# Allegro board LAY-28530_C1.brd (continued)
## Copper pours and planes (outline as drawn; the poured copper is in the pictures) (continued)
GND on L2_GND: 207.32,167.46 214.61,167.46 214.61,1.83 213.84,1.06 97.34,1.06 96.58,1.83 3.49,1.83 1.45,3.86 1.45,166.93 1.83,167.31 70.16,167.31 70.16,153.46 66.86,150.16 66.86,129.21 88.96,129.21 92.26,132.51 92.26,156.51 138.74,156.51 140.58,154.67 167.63,154.67 171.76,158.8 171.76,165.28 173.03,166.55 180.52,166.55 182.56,164.51 182.56,161.97 184.97,159.56 190.94,159.56 191.95,160.58 201.73,160.58 202.62,159.69 206.56,159.69 207.32,160.45 ; 9 cut-outs
GND on L5_PWR: 112.82,41.35 112.82,35.42 108.74,31.34 108.74,19.1 114.97,12.88 174.94,12.88 174.94,30.91 165.16,30.91 164.39,31.67 164.39,41.07 156.65,48.82 156.65,52.75 150.04,59.36 146.87,59.36 146.36,59.87 145.22,59.87 143.68,61.4 136.3,61.4 135.42,60.52 132.47,60.52 128.18,56.23 127.7,56.23
GND on L5_PWR: 67.49,167.18 1.96,167.18 1.07,166.29 1.07,4.62 3.1,2.59 70.41,2.59 71.68,3.86 71.68,32.94 53.02,51.61 23.81,51.61 22.28,53.13 22.28,98.09 41.97,117.78 41.97,147.75 44.38,150.16 66.86,150.16 68.26,151.56 68.26,166.42 ; 4 cut-outs
GND on L5_PWR: 171.89,159.56 207.45,159.56 207.45,167.43 214.94,167.43 215.19,167.18 215.19,151.56 208.97,151.56 208.97,153.21 174.05,153.21 173.92,153.08 173.92,148.38 172.14,148.38 167.32,143.56 138.87,143.56 138.87,130.35 92.26,130.35 92.26,148.26 93.15,149.15 100.26,149.15 106.61,155.5 167.82,155.5
GND_EARTH on TOP: 188.91,160.07 188.91,165.66 189.79,166.55 206.05,166.55 206.56,166.04 206.56,160.45 205.67,159.56 203.26,159.56 202.24,160.58 191.95,160.58 190.94,159.56 189.41,159.56
GND_EARTH on BOTTOM: 124.39,165.78 124.39,161.59 128.71,161.59 128.71,165.78
GND_EARTH on BOTTOM: 111.18,168.58 111.56,168.96 117.79,168.96 118.55,168.2 118.55,161.47 118.42,161.34 111.18,161.34
GND_EARTH on BOTTOM: 168.97,157.91 168.97,161.34 168.46,161.85 164.14,161.85 163.51,161.21 163.51,158.04 163.89,157.66 168.71,157.66
GND_EARTH on L2_GND: 141.92,157.4 141.41,157.91 141.41,162.48 140.39,163.5 92.26,163.5 92.13,163.62 92.13,168.83 206.81,168.83 206.81,161.08 205.92,160.2 203.13,160.2 201.86,161.47 191.83,161.47 190.56,160.2 185.73,160.2 183.44,162.48 183.44,165.66 181.67,167.43 172.4,167.43 170.87,165.91 170.87,159.94 168.33,157.4 ; 1 cut-out
GND_EARTH on L5_PWR: 159.06,167.46 206.56,167.46 206.56,160.45 206.3,160.2 171.13,160.2 168.33,157.4 158.81,157.4 158.55,157.66 158.55,166.95
GND_SIGNAL on TOP: 82.61,150.16 83.24,149.53 83.24,146.1 82.86,145.72 79.3,145.72 78.92,145.34 78.92,143.69 78.8,143.56 75.75,143.56 75.49,143.81 75.49,152.83 75.75,153.08 82.1,153.08 82.61,152.58
GND_SIGNAL on TOP: 78.54,139.24 79.94,139.24 80.7,138.48 80.7,134.92 81.08,134.54 86.67,134.54 87.18,134.03 87.18,132.26 86.04,131.11 79.3,131.11 78.16,132.26 78.16,138.86
GND_SIGNAL on BOTTOM: 78.03,135.18 78.03,130.48 78.8,129.72 87.81,129.72 88.19,130.1 88.19,135.18 87.56,135.81 78.67,135.81
GND_SIGNAL on L2_GND: 71.43,151.18 68.26,148 68.26,130.1 87.94,130.1 91.37,133.53 91.37,168.15 90.3,169.21 72.07,169.21 71.43,168.58
GND_SIGNAL on L5_PWR: 68.26,138.61 68.26,148 71.43,151.18 71.43,168.58 72.07,169.21 90.48,169.21 90.73,168.96 91.24,168.96 91.37,168.83 91.37,138.61
12 on TOP: 73.34,165.66 73.34,168.83 73.46,168.96 76.89,168.96 77.15,168.7 77.15,165.66 76.76,165.28 73.72,165.28
12 on BOTTOM: 149.15,165.15 149.15,166.8 148.9,167.05 146.49,167.05 146.23,166.8 146.23,164.89 146.49,164.64 147.5,164.64 147.88,165.02 149.03,165.02
12 on BOTTOM: 92,152.45 94.8,152.45 94.93,152.32 94.93,151.05 94.8,150.92 91.88,150.92 91.75,151.05 91.75,152.19
12 on BOTTOM: 73.34,165.66 73.34,168.83 73.46,168.96 76.89,168.96 77.15,168.7 77.15,165.66 76.76,165.28 73.72,165.28
12 on L4_INT2: 86.04,161.21 78.29,168.96 74.86,168.96 74.61,168.7 74.61,167.05 83.62,158.04 89.59,158.04 90.23,157.4 90.23,153.97 93.53,150.67 94.8,150.67 95.05,150.92 95.05,152.58 92.77,154.86 92.77,158.67 90.23,161.21
12 on L5_PWR: 147.76,166.16 146.23,166.16 145.22,165.15 140.9,165.15 136.71,160.96 102.42,160.96 99.05,157.59 99.05,154.92 96.96,152.83 93.02,152.83 92.64,152.45 92.64,150.92 93.4,150.16 99.62,150.16 106.1,156.64 143.44,156.64 148.01,161.21 148.01,165.91
34 on TOP: 82.23,165.66 82.23,168.83 82.35,168.96 85.78,168.96 86.04,168.7 86.04,165.66 85.65,165.28 82.61,165.28
34 on BOTTOM: 82.23,165.66 82.23,168.83 82.35,168.96 85.78,168.96 86.04,168.7 86.04,165.66 85.65,165.28 82.61,165.28
34 on BOTTOM: 149.79,164.77 151.82,164.77 151.95,164.89 151.95,166.8 151.69,167.05 149.54,167.05 149.41,166.93 149.41,165.15
34 on BOTTOM: 102.55,152.45 105.34,152.45 105.47,152.32 105.47,151.31 105.21,151.05 102.55,151.05 102.42,151.18 102.42,152.32
34 on L4_INT2: 84.77,168.96 89.97,168.96 92.51,166.42 92.51,162.74 95.05,160.2 99.5,160.2 127.44,160.2 127.56,160.07 134.93,160.07 138.99,164.13 147.63,164.13 148.65,165.15 148.65,167.05 149.41,167.82 151.31,167.82 151.95,167.18 151.95,163.24 148.9,160.2 142.17,160.2 138.87,156.89 106.1,156.89 104.96,155.75 104.96,154.73 106.1,153.59 106.1,150.92 105.85,150.67 103.43,150.67 103.18,150.92 103.18,152.96 98.86,157.27 95.05,157.27 90.61,161.72 86.54,161.72 84.26,164.01 84.26,168.45
56 on TOP: 77.78,165.66 77.78,168.83 77.91,168.96 81.34,168.96 81.59,168.7 81.59,165.66 81.21,165.28 78.16,165.28
56 on BOTTOM: 77.78,165.66 77.78,168.83 77.91,168.96 81.34,168.96 81.59,168.7 81.59,165.66 81.21,165.28 78.16,165.28
56 on BOTTOM: 152.33,164.77 154.23,164.77 154.49,165.02 154.49,166.93 154.36,167.05 152.33,167.05 152.2,166.93 152.2,164.89
56 on BOTTOM: 91.88,156.89 94.67,156.89 94.8,157.02 94.8,158.42 94.54,158.67 91.75,158.67 91.62,158.54 91.62,157.15
56 on L3_INT1: 85.91,157.4 79.69,163.62 79.69,168.7 80.07,169.09 83.88,169.09 84.38,168.58 84.38,166.29 88.19,162.48 90.99,162.48 95.05,158.42 95.05,156.51 94.93,156.39 92.13,156.39 91.12,157.4
56 on L5_PWR: 93.15,156.64 96.07,156.64 102.67,163.24 135.95,163.24 139.38,166.67 147.88,166.67 149.92,164.64 154.23,164.64 154.62,165.02 154.62,168.45 154.11,168.96 94.67,168.96 92.64,166.93 92.64,157.15
78 on TOP: 86.54,165.66 86.54,168.83 86.67,168.96 90.1,168.96 90.35,168.7 90.35,165.66 89.97,165.28 86.92,165.28
78 on BOTTOM: 157.28,164.77 156.27,164.77 156.01,165.02 154.87,165.02 154.74,165.15 154.74,166.55 155.12,166.93 157.28,166.93 157.54,166.67 157.54,165.02
78 on BOTTOM: 86.54,165.66 86.54,168.83 86.67,168.96 90.1,168.96 90.35,168.7 90.35,165.66 89.97,165.28 86.92,165.28
78 on BOTTOM: 102.67,157.02 105.59,157.02 105.72,157.15 105.72,158.8 105.47,159.05 102.67,159.05 102.42,158.8 102.42,157.27
78 on L3_INT1: 102.61,168.77 111.18,160.2 134.42,160.2 137.85,163.62 153.85,163.62 155.25,165.02 155.25,167.05 155.63,167.43 157.66,167.43 157.92,167.18 157.92,164.13 154.49,160.7 141.92,160.7 137.47,156.26 104.07,156.26 102.42,157.91 102.42,161.34 100.13,163.62 90.35,163.62 88.58,165.4 88.58,168.45 88.89,168.77
ADP_12V on TOP: 100.01,95.93 100.01,101.01 99.62,101.39 96.7,101.39 95.69,102.41 95.69,108.25 95.31,108.63 88.19,108.63 87.94,108.38 87.94,103.81 87.56,103.43 83.11,103.43 82.73,103.05 82.73,99.36 82.99,99.11 90.99,99.11 91.88,98.22 91.88,88.69 92.39,88.19 96.7,88.19 99.37,90.85 99.37,95.3
AQR105_FLASH on L5_PWR: 165.28,131.37 164.27,132.38 153.47,132.38 153.22,132.13 153.22,126.92 152.58,126.29 139.5,126.29 139.5,142.67 167.44,142.67 172.4,147.62 179.25,147.62 181.41,145.46 181.41,121.21 180.65,120.44 166.55,120.44 165.28,121.71 ; 3 cut-outs
AQR105_VA12 on TOP: 144.07,125.78 147.88,125.78 148.27,125.4 148.27,119.17 146.23,117.14 146.23,112.57 145.85,112.19 144.71,112.19 144.58,112.06 144.58,111.05 143.82,111.05 143.82,112.7 144.2,113.08 144.2,115.24 143.69,115.75 143.69,125.4
AQR105_VA12 on L4_INT2: 158.17,134.41 147.25,134.41 143.19,130.35 143.19,124.76 143.69,124.25 148.01,124.25 149.15,125.4 149.15,129.33 151.06,131.24 158.04,131.24 158.55,131.75 158.55,134.03
AQR105_VA12 on L4_INT2: 139.88,69.77 138.49,69.77 138.23,70.03 138.23,74.72 138.49,74.98 138.61,74.85 139.63,74.85 139.88,74.6
AQR105_VA22 on TOP: 141.15,137.21 144.2,137.21 144.71,136.7 144.71,132.38 144.46,132.13 141.28,132.13 141.03,132.38 136.58,132.38 136.33,132.64 136.33,135.3 136.58,135.56 139.5,135.56
AQR105_VA22 on TOP: 137.34,114.73 137.34,116.38 137.6,116.63 138.74,116.63 138.99,116.38 138.99,112.19 138.87,112.06 138.11,112.06 137.98,111.94 137.98,111.05 137.22,111.05 137.22,112.7 137.6,113.08 137.6,114.48
AQR105_VA22 on TOP: 149.66,116.25 149.66,108.38 150.3,107.74 152.71,107.74 153.09,108.13 153.09,113.08 152.33,113.84 152.33,118.67 152.08,118.92 149.15,118.92 148.9,118.67 148.9,117.02
AQR105_VA22 on L4_INT2: 151.57,126.16 153.35,126.16 153.73,125.78 153.73,118.67 152.08,117.02 142.17,117.02 139.76,114.6 136.2,114.6 135.69,115.11 135.69,119.17 138.61,122.1 138.61,134.16 141.79,137.34 143.44,137.34 145.09,138.99 159.19,138.99 159.95,138.22 159.95,135.43 159.19,134.67 145.98,134.67 142.3,130.99 142.3,123.87 143.44,122.73 148.14,122.73
AQR105_VDD on TOP: 198.68,127.56 193.86,127.56 192.84,126.54 178.75,126.54 178.75,117.52 175.95,114.73 175.95,109.52 176.21,109.27 179.13,109.27 180.27,110.41 191.45,110.41 191.95,110.92 191.95,119.56 192.72,120.32 199.07,120.32 199.83,121.08 199.83,126.41
AQR105_VDD on L5_PWR: 153.73,131.62 164.14,131.62 164.52,131.24 164.52,120.57 165.92,119.17 180.78,119.17 180.78,110.03 154.36,110.03 153.73,110.67
DCDC1_3V3 on TOP: 80.96,54.02 79.3,55.67 79.3,58.6 79.69,58.98 84.51,58.98 84.64,58.85 84.64,54.28 84.38,54.02 84.38,47.93 85.15,47.17 85.78,47.17 86.16,46.78 86.16,42.97 86.04,42.85 81.21,42.85 80.96,43.1
DCDC1_3V3 on BOTTOM: 121.6,127.81 117.66,127.81 117.15,127.3 117.15,124.13 117.79,123.49 121.34,123.49 121.85,124 121.85,127.56
DCDC1_3V3 on L5_PWR: 76.64,56.18 76,56.82 76,62.79 69.27,69.52 69.27,81.71 58.86,92.12 51.11,92.12 49.08,94.16 49.08,145.97 49.46,146.35 54.67,146.35 71.68,129.33 120.2,129.33 120.2,123.75 99.75,123.75 99.75,89.08 85.53,89.08 85.53,56.18 ; 1 cut-out
DCDC2_3V3 on TOP: 102.04,39.04 102.04,32.43 104.2,30.27 104.2,26.85 103.82,26.46 98.35,26.46 96.96,27.86 96.96,33.2 96.2,33.96 79.43,33.96 77.78,35.61 77.78,51.74 77.91,51.86 79.94,51.86 80.45,51.36 80.45,37.39 81.21,36.62 92.26,36.62 94.93,39.29 101.78,39.29
DCDC2_3V3 on TOP: 94.93,14.53 95.18,14.27 95.18,14.02 94.93,13.76 94.8,13.76 94.16,14.4 94.16,16.18 94.93,16.18
DCDC2_3V3 on TOP: 144.71,105.84 136.58,105.84 136.45,105.71 136.45,104.7 136.58,104.57 144.84,104.57 144.96,104.7 144.96,105.59
DCDC2_3V3 on TOP: 97.47,19.23 99.12,19.23 99.37,18.97 99.37,18.21 98.35,18.21 98.1,18.46 98.1,18.84 97.97,18.97 97.47,18.97
DCDC2_3V3 on BOTTOM: 98.48,126.16 98.48,122.22 99.37,121.33 103.56,121.33 103.69,121.46 103.69,122.35 103.18,122.86 101.53,122.86 101.02,123.37 101.02,126.67 100.77,126.92 99.24,126.92
DCDC2_3V3 on L4_INT2: 170.74,88.82 170.74,86.28 173.79,86.28 173.79,88.82
DCDC2_3V3 on L4_INT2: 141.79,66.85 139.38,66.85 138.61,67.61 138.61,68.5 137.98,69.14 135.82,69.14 134.3,70.66 134.3,73.33 127.82,79.8 123.25,79.8 122.87,80.19 122.87,82.09 123.37,82.6 127.95,82.6 137.47,73.07 137.47,70.53 138.49,69.52 139.88,69.52 141.03,68.37 141.53,68.37 141.79,68.12
DCDC2_3V3 on L5_PWR: 114.86,7.03 114.23,6.4 103.18,6.4 101.15,8.43 101.15,13.64 101.91,14.4 105.72,14.4 108.01,16.69 108.01,31.8 112.07,35.86 112.07,56.94 110.29,58.72 108.26,58.72 108.13,58.85 108.13,76.25 111.44,79.55 123.88,79.55 130.61,86.28 179.76,86.28 179.76,82.34 184.84,82.34 184.84,90.22 179.76,90.22 179.76,97.2 172.78,97.2 172.65,97.33 172.65,102.03 187.89,102.03 187.89,104.82 203.89,104.82 203.89,143.69 208.21,143.69 208.21,152.58 174.94,152.58 174.81,152.45 174.81,148.26 179.51,148.26 182.3,145.46 182.3,109.14 152.96,109.14 152.96,125.52 135.95,125.52 135.82,125.65 135.82,129.33 121.21,129.33 121.21,123.11 100.51,123.11 100.51,88.31 86.29,88.31 86.29,55.29 85.65,54.66 76.26,54.66 74.48,56.44 74.48,62.53 68.26,68.76 68.26,81.07 65.21,84.12 50.86,84.12 49.59,82.85 49.59,69.01 86.29,32.31 86.29,1.7 97.08,1.7 97.34,1.45 214.18,1.45 214.31,1.57 214.31,23.67 213.8,24.18 181.29,24.18 181.29,7.03 ; 3 cut-outs
DCDC_1V0 on BOTTOM: 111.69,58.98 111.44,58.72 109.28,58.72 109.15,58.85 109.15,59.61 108.77,59.99 108.77,63.04 109.15,63.42 110.04,63.42 110.29,63.68 110.29,66.72 110.55,66.98 111.56,66.98 111.69,66.85
DCDC_1V0 on L3_INT1: 109.28,63.04 114.86,63.04 116.52,61.39 126.42,61.39 130.1,65.07 136.45,65.07 136.71,65.33 136.71,67.36 136.96,67.61 144.33,67.61 144.71,67.23 144.71,61.39 144.46,61.14 131.25,61.14 127.95,57.83 124.39,57.83 121.6,55.04 109.91,55.04 109.02,55.93 109.02,62.79
DCDC_1V0 on L5_PWR: 144.07,61.77 129.47,61.77 127.18,59.48 109.53,59.48 108.77,60.25 108.77,75.36 109.4,75.99 119.06,75.99 120.33,74.72 136.33,74.72 136.33,67.61 136.84,67.1 143.95,67.1 144.96,68.12 155.76,68.12 157.28,69.64 158.04,69.64 158.43,69.26 158.43,68.76 155.89,66.22 144.71,66.22 144.07,65.58
DCDC_1V0_SUP on TOP: 104.32,63.93 99.12,63.93 98.61,63.42 98.61,60.75 97.59,59.74 87.69,59.74 87.18,59.23 87.18,57.2 87.69,56.69 91.24,56.69 91.5,56.94 99.12,56.94 100.26,58.09 105.59,58.09 106.36,58.85 106.36,61.9
DCDC_1V0_SUP on BOTTOM: 103.18,63.04 103.18,60.25 103.43,59.99 105.97,59.99 106.23,60.25 106.23,62.91 105.97,63.17 103.31,63.17
DCDC_5V0 on TOP: 184.97,139.88 183.44,139.88 183.06,139.49 183.06,137.84 183.32,137.59 188.4,137.59 189.03,138.22 189.03,140.38 188.02,141.4 188.02,145.59 188.4,145.97 189.79,145.97 189.79,147.62 189.54,147.88 186.24,147.88 185.22,146.86 185.22,140.13
DDR4_VDD on TOP: 102.8,24.94 103.05,25.19 106.36,25.19 106.61,24.94 106.61,16.69 106.48,16.56 103.05,16.56 102.8,16.81
DDR4_VDD on BOTTOM: 131.63,13.38 145.6,13.38 148.9,10.08 164.65,10.08 167.06,12.49 167.06,27.61 168.46,29 168.46,37.01 143.44,62.02 137.34,62.02 136.84,61.52 136.84,60.88 135.82,59.87 132.9,59.87 121.88,48.85 121.88,48.57 121.5,48.2 121.41,48.2 121.41,45.45 111.5,35.54 111.5,31.35 107.12,26.97 103.56,26.97 102.42,25.83 102.42,22.78 108.62,16.58 108.62,13.69 109.05,13.26 124.9,13.26 124.96,13.32 131.57,13.32 ; 28 cut-outs
DDR4_VTT on TOP: 86.92,9.57 87.18,9.83 93.15,9.83 93.4,9.57 93.4,6.91 94.16,6.14 106.1,6.14 109.28,9.32 109.28,11.86 110.04,12.62 165.41,12.62 166.93,11.1 169.98,11.1 169.98,27.48 169.73,27.73 169.73,28.75 169.86,28.88 173.03,28.88 173.28,28.62 173.28,8.94 172.9,8.56 163.76,8.56 162.49,9.83 114.99,9.83 108.39,3.22 93.02,3.22 92.51,2.72 87.05,2.72 86.92,2.84
DDR4_VTT on BOTTOM: 111.05,12.75 110.93,12.62 109.66,12.62 109.4,12.37 109.4,11.73 110.42,10.72 118.67,10.72 119.06,11.1 119.06,12.24 118.55,12.75
DDR4_VTT on BOTTOM: 173.28,9.45 172.14,8.3 170.11,8.3 169.98,8.43 169.98,27.35 169.86,27.48 169.47,27.48 169.09,27.86 169.09,28.75 169.22,28.88 173.16,28.88 173.28,28.75
LDO_1V0 on TOP: 107.88,55.67 107.88,55.17 106.86,55.17 106.86,54.4 107.75,54.4 108.13,54.02 110.55,54.02 110.93,54.4 110.93,55.42 110.67,55.67
PCIE_3V3 on TOP: 76.76,47.04 76.76,50.72 76.64,50.85 72.32,50.85 72.19,50.72 72.19,47.55 72.7,47.04
PCIE_3V3 on L3_INT1: 24.06,55.17 24.06,57.83 28.63,62.41 30.03,62.41 34.16,58.28 71.24,58.28 74.99,54.53 74.99,48.94 74.22,48.18 71.56,48.18 70.54,49.2 70.54,52.88 68.64,54.79 24.44,54.79
POE_12V on TOP: 82.99,117.78 94.8,117.78 95.43,117.14 95.43,110.92 95.05,110.54 88.83,110.54 86.92,112.44 83.5,112.44 82.99,112.95
TRCT on TOP: 145.85,153.85 145.85,152.07 147.63,152.07 147.63,153.85
VPA on TOP: 24.82,63.04 27.74,63.04 27.74,73.84 24.82,76.76 5.01,76.76 5.01,74.22 8.06,71.17 22.28,71.17 22.28,66.72 24.82,64.18
VPA_PCIE2 on TOP: 44.38,90.85 43.87,90.35 43.87,76.25 44.13,75.99 46.54,75.99 49.59,79.04 49.59,90.85
VPA_PCIE2 on TOP: 55.3,146.48 55.17,146.35 55.17,142.54 59.87,142.54 60.64,141.78 60.64,138.22 58.98,136.57 58.98,133.65 62.16,133.65 62.16,145.97 61.65,146.48
VPA_PCIE2 on L4_INT2: 56.83,136.7 62.67,136.7 62.67,97.71 52.25,87.3 43.87,87.3 43.87,90.85 47.05,90.85 56.83,100.63
VR500_1V5 on TOP: 83.88,21.13 83.24,21.77 83.24,31.42 82.73,31.93 79.3,31.93 79.18,31.8 79.18,13.89 79.94,13.13 83.5,13.13 83.88,13.51
VR500_1V5 on L5_PWR: 24.31,52.75 54.03,52.75 74.22,32.56 74.22,25.32 75.11,24.43 82.99,24.43 83.37,24.81 83.37,32.18 47.94,67.61 47.94,147.62 47.68,147.88 44.51,147.88 44.13,147.5 44.13,116.51 23.81,96.19 23.81,53.26
N24081686 on TOP: 85.02,21.51 87.56,21.51 87.81,21.26 87.81,19.99 88.07,19.73 89.72,19.73 89.72,18.97 88.07,18.97 87.81,18.72 87.81,16.56 87.31,16.05 85.15,16.05 84.89,16.3 84.89,21.38
N24082962 on TOP: 93.66,10.21 93.78,10.08 98.23,10.08 98.48,10.34 98.48,12.11 96.96,13.64 94.54,13.64 93.91,14.27 93.91,16.18 93.66,16.18
N24084401 on TOP: 97.47,20.24 99.24,20.24 99.62,20.62 99.62,21.26 100.39,22.02 101.28,22.02 101.53,21.77 101.53,17.45 101.4,17.32 100.26,17.32 100.01,17.57 100.01,18.97 99.5,19.48 97.47,19.48 97.34,19.61 97.34,20.11
N24085678 on TOP: 93.4,10.46 93.02,10.08 88.7,10.08 88.45,10.34 88.45,12.37 88.83,12.75 91.5,12.75 93.15,14.4 93.15,16.18 93.4,16.18
N24105172 on TOP: 72.83,164.26 72.45,163.88 72.45,151.18 69.14,147.88 69.14,145.97 70.03,145.08 73.72,145.08 73.84,145.21 73.84,148.51 74.73,149.4 74.73,154.73 75.11,155.12 76.89,155.12 77.27,155.5 77.27,160.7 77.78,161.21 86.92,161.21 87.18,160.96 87.18,159.94 87.69,159.43 90.1,159.43 90.35,159.69 90.35,163.88 89.97,164.26
N24105172 on BOTTOM: 72.57,160.32 74.73,160.32 75.11,159.94 75.11,155.5 74.73,155.12 72.7,155.12 72.45,155.37 72.45,160.2
N24105186 on TOP: 87.69,154.86 87.69,158.67 87.94,158.93 90.48,158.93 90.73,158.67 90.73,154.48 89.72,154.48 89.72,155.37 90.23,155.88 90.23,156.51 89.85,156.89 88.83,156.89 88.7,156.77 88.7,156.26 88.32,155.88 88.32,154.86
N24105186 on BOTTOM: 84.13,161.21 79.05,161.21 78.42,160.58 78.42,157.78 78.29,157.66 76.26,157.66 75.88,158.04 75.88,160.83 75.49,161.21 73.46,161.21 73.21,161.47 73.21,164.77 73.46,165.02 88.32,165.02 89.08,164.26 89.08,159.56 90.73,157.91 90.73,156.13 90.48,155.88 89.59,155.88 89.21,156.26 88.58,156.26 88.19,155.88 87.81,155.88 87.56,156.13 87.56,156.51 86.67,157.4 86.16,157.4 85.65,157.91 85.65,159.69
N24106733 on BOTTOM: 86.67,154.23 86.67,157.02 86.54,157.15 85.65,157.15 85.27,157.53 85.27,159.31 85.02,159.56 83.37,159.56 83.24,159.43 83.24,158.04 85.4,155.88 85.4,154.48 85.78,154.1 86.54,154.1
N24106981 on TOP: 75.24,139.75 79.81,139.75 80.07,140 80.07,142.54 79.94,142.67 69.02,142.67 68.76,142.42 68.76,139.24 69.27,138.73 74.22,138.73
N24106981 on TOP: 86.16,135.81 88.96,135.81 89.59,136.45 89.59,139.37 89.46,139.49 86.29,139.49 85.91,139.11 85.91,136.07
N24106981 on BOTTOM: 81.59,142.8 82.48,141.91 82.48,139.88 82.73,139.62 89.21,139.62 89.46,139.37 89.46,137.08 89.34,136.95 77.78,136.95 77.27,137.46 77.27,142.67 77.4,142.8
N24107470 on TOP: 86.42,154.73 86.42,155.37 86.67,155.62 86.67,156.64 86.8,156.77 87.31,156.77 87.43,156.64 87.43,155.24 86.8,155.24 86.8,154.73
N24107950 on TOP: 86.29,118.54 86.29,122.73 86.67,123.11 88.45,123.11 89.34,122.22 93.15,122.22 93.27,122.1 93.27,118.54 93.02,118.29 86.54,118.29
N24107950 on BOTTOM: 88.96,123.62 93.27,123.62 93.53,123.37 93.53,115.87 92.77,115.11 89.08,115.11 88.7,115.49 88.7,123.37
N24108405 on BOTTOM: 93.53,127.81 94.04,127.3 94.04,124.76 93.78,124.51 90.1,124.51 89.59,125.02 89.59,127.3 90.1,127.81
N24108768 on TOP: 77.78,122.48 77.78,113.33 77.53,113.08 73.84,113.08 73.59,113.33 73.59,122.35 74.22,122.98 77.27,122.98
N24108952 on TOP: 86.67,140.38 88.83,140.38 88.96,140.51 88.96,143.81 88.83,143.94 86.8,143.94 86.54,144.19 86.54,148.13 86.29,148.38 85.15,148.38 85.02,148.26 85.02,144.19 86.29,142.92 86.29,140.76
N24133241 on TOP: 62.29,159.18 64.06,160.96 68,160.96 68.64,160.32 68.64,158.16 67.94,157.46 67.94,154.54 67.94,152.77 66.22,151.05 62.92,151.05 62.29,151.69
N24137912 on TOP: 91.12,63.68 91.37,63.42 95.81,63.42 96.32,62.91 96.32,60.63 96.07,60.37 90.86,60.37 90.35,60.88 90.35,63.68
N24194949 on TOP: 179.25,108.51 176.08,108.51 175.44,109.14 175.44,115.49 174.94,116 170.87,116 170.49,115.62 170.49,104.19 171.51,103.17 178.49,103.17 179.51,104.19 179.51,108.25
N24194949 on L4_INT2: 154.49,123.62 155.76,123.62 156.77,122.6 164.78,122.6 174.43,112.95 174.43,110.16 173.92,109.65 170.74,109.65 162.36,118.03 155.25,118.03 154.23,119.05 154.23,123.37
N24197224 on TOP: 157.41,117.9 162.24,117.9 162.62,117.52 162.62,113.33 162.11,112.82 157.54,112.82 156.77,113.59 156.77,117.27
N24197929 on TOP: 169.73,147.75 169.73,142.8 169.98,142.54 173.67,142.54 173.92,142.8 173.92,148 173.67,148.26 170.24,148.26
N24197929 on BOTTOM: 159.7,135.3 160.58,135.3 169.98,144.7 172.14,144.7 172.52,144.32 172.52,142.8 163.25,133.53 159.57,133.53 159.31,133.78 159.31,134.92
N24198270 on TOP: 167.57,133.4 167.95,133.4 168.46,133.91 169.73,133.91 171,135.18 172.65,135.18 173.41,135.94 173.41,141.65 173.03,142.03 169.86,142.03 168.71,140.89 168.71,135.43 167.32,134.03 167.32,133.65
N24220381 on BOTTOM: 144.33,67.87 145.93,67.87 146.31,68.25 150.42,68.25 151.57,67.1 158.43,67.1 158.55,66.98 158.55,65.83 158.43,65.71 150.17,65.71 149.79,66.09 146.74,66.09 145.66,67.17 144.39,67.17 144.2,67.36 144.2,67.74
N24221237 on BOTTOM: 148.01,71.04 146.49,71.04 145.55,70.1 145.55,68.63 145.22,68.63 145.09,68.5 145.09,68.12 145.22,67.99 145.68,67.99 146.31,68.63 150.42,68.63 150.81,69.01 156.52,69.01 156.77,69.26 156.77,70.28 156.65,70.41 150.04,70.41 149.54,69.9 148.39,69.9 148.14,70.15 148.14,70.91
N24221789 on BOTTOM: 147.25,65.2 148.77,65.2 149.03,64.95 157.66,64.95 157.79,64.82 157.79,63.93 157.54,63.68 146.11,63.68 144.2,65.58 144.2,66.95 144.28,67.03 145.09,67.03 145.09,66.98 145.34,66.72 145.37,66.72 145.42,66.77 145.42,66.72 145.73,66.72
N24245830 on L4_INT2: 136.71,62.41 136.71,66.6 136.33,66.98 133.53,66.98 127.95,61.39 118.93,61.39 118.04,62.28 118.04,64.06 118.17,64.18 118.6,64.18 120.68,66.27 123.88,66.27 124.91,67.29 130.42,67.29 131.88,68.76 137.72,68.76 138.36,68.12 138.36,62.41
N24247836 on L4_INT2: 134.3,66.22 128.83,60.75 119.31,60.75 118.29,59.74 118.29,57.33 118.8,56.82 127.69,56.82 132.26,61.39 135.57,61.39 136.07,61.9 136.07,66.09 135.95,66.22
N24271066 on L4_INT2: 147.38,59.99 150.3,59.99 152.58,57.71 155.63,57.71 155.89,57.45 155.89,57.07 155.63,56.82 151.95,56.82 150.81,57.96 142.68,57.96 141.92,58.72 141.92,59.61 141.53,59.99 141.53,61.77 141.66,61.9 145.47,61.9
N24302177 on TOP: 130.61,128.45 131.63,128.45 131.88,128.19 131.88,122.22 131.63,121.97 125.79,121.97 125.41,122.35 125.41,124.85 125.7,125.14 130.23,125.14 130.36,125.27 130.36,128.19
N24378377 on TOP: 199.07,160.07 199.32,160.32 202.11,160.32 202.49,159.94 202.49,158.04 201.22,156.77 201.22,153.72 200.97,153.46 199.7,153.46 199.07,154.1
N24379468 on TOP: 191.95,145.97 193.48,145.97 193.86,145.59 196.78,145.59 198.24,144.13 198.24,144.07 199.13,143.18 201.73,143.18 202.81,144.26 202.81,144.89 204.53,146.61 204.53,156 203.89,156.64 201.86,156.64 201.48,156.26 201.48,154.48 202.37,153.59 202.37,148.38 201.99,148 199.83,148 199.07,147.24 198.18,147.24 197.92,147.5 192.21,147.5 191.95,147.24
N24480273 on TOP: 183.44,134.92 189.29,134.92 189.92,134.29 191.45,134.29 191.45,136.32 190.81,136.95 183.32,136.95 183.06,136.7 183.06,135.3
N24506783 on TOP: 92.64,51.1 90.35,51.1 87.56,53.9 86.16,53.9 86.04,53.77 86.04,48.05 86.42,47.67 89.46,47.67 90.35,48.56 91.5,48.56 91.88,48.18 92.64,48.18
N24509767 on TOP: 105.21,40.56 104.83,40.18 104.83,38.66 105.59,37.89 105.59,33.7 105.47,33.58 103.43,33.58 103.18,33.83 103.18,38.66 102.42,39.42 102.42,41.2 102.55,41.32 105.21,41.32
N24935830 on TOP: 82.48,135.94 82.48,138.48 83.62,139.62 83.62,145.08 83.5,145.21 80.96,145.21 80.57,144.83 80.57,139.88 81.21,139.24 81.21,135.94
N24935830 on BOTTOM: 83.5,143.18 83.5,145.08 83.11,145.46 80.45,145.46 80.07,145.08 80.07,143.69 80.57,143.18
N24935853 on BOTTOM: 84.64,140.76 84.64,144.45 84.89,144.7 86.54,144.7 86.67,144.57 86.67,140.76 86.42,140.51 84.89,140.51
N24996629 on TOP: 97.34,114.73 97.34,116.51 97.59,116.76 103.94,116.76 104.7,116 104.7,106.86 104.32,106.47 97.59,106.47 97.34,106.73 97.34,108.76 97.72,109.14 101.78,109.14 102.16,109.52 102.16,114.22 101.78,114.6 97.47,114.6
N25157741 on TOP: 193.22,114.09 192.46,114.86 192.46,118.79 192.97,119.3 199.32,119.3 200.59,118.03 204.78,118.03 205.03,117.78 205.03,116.13 204.15,116.13 204.02,116 204.02,114.09
N26669717 on TOP: 15.17,83.36 9.2,83.36 8.95,83.11 8.95,79.04 9.2,78.79 14.28,78.79 14.53,79.04 14.53,81.84 15.17,82.47
N26747830 on BOTTOM: 154.11,164.13 154.11,162.48 153.73,162.1 153.73,158.42 154.11,158.04 154.11,156.51 154.62,156 155.63,156 155.89,156.26 155.89,157.66 155.12,158.42 155.12,162.1 156.14,163.12 156.14,164.13 155.89,164.39 154.36,164.39
N26747833 on BOTTOM: 153.6,164.26 152.33,164.26 152.2,164.13 152.2,156.39 152.58,156 153.47,156 153.85,156.39 153.85,157.78 153.47,158.16 153.47,162.48 153.85,162.86 153.85,164.01
N26747836 on BOTTOM: 150.42,164.26 151.44,164.26 151.95,163.75 151.95,156.39 151.57,156 150.42,156 150.04,156.39 150.04,157.53 150.42,157.91 150.42,162.35 150.04,162.74 150.04,163.88
N26747839 on BOTTOM: 149.79,162.48 150.17,162.1 150.17,158.29 149.79,157.91 149.79,156.39 149.41,156 148.27,156 148.01,156.26 148.01,157.4 148.9,158.29 148.9,161.85 147.76,162.99 147.76,164.26 147.88,164.39 149.41,164.39 149.79,164.01
N26748165 on BOTTOM: 92.13,154.35 95.43,154.35 95.69,154.61 97.21,154.61 97.59,154.23 97.59,152.7 94.93,152.7 94.67,152.96 92,152.96 91.88,153.08 91.88,154.1
N26748168 on BOTTOM: 102.67,152.96 105.72,152.96 106.1,152.58 108.77,152.58 109.02,152.83 109.02,154.35 108.9,154.48 102.67,154.48 102.42,154.23 102.42,153.21
N26748171 on BOTTOM: 91.88,156.39 94.8,156.39 95.05,156.64 97.21,156.64 97.47,156.39 97.47,155.24 97.08,154.86 92,154.86 91.62,155.24 91.62,156.13
N26748174 on BOTTOM: 102.55,156.51 105.72,156.51 106.23,157.02 108.64,157.02 109.02,156.64 109.02,155.24 108.77,154.99 102.67,154.99 102.29,155.37 102.29,156.26
N26901046 on TOP: 37.27,86.15 37.27,80.82 37.52,80.57 41.71,80.57 41.84,80.69 41.84,84.88 41.46,85.27 39.05,85.27 38.16,86.15

Small or netless copper shapes (teardrops, artwork), in the pictures only: 1 on TOP

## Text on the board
BOTTOM: 9 OF 12 | SECONDARY SIDE | 170-28530 REV C1
Board Geometry/Soldermask Bottom: 10 OF 12 | SECONDARY SOLDERMASK
Package Geometry/Pastemask Bottom: 12 OF 12 | SECONDARY PASTEMASK
Ref Des/Silkscreen Bottom: 11 OF 12 | SECONDARY SILKSCREEN
User.Comments: 1     1
TOP: 4 OF 12 | PRIMARY SIDE
Board Geometry/Soldermask Top: 3 OF 12 | PRIMARY SOLDERMASK
Package Geometry/Pastemask Top: 1 OF 12 | PRIMARY PASTEMASK
Ref Des/Silkscreen Top: 7-8:3.3V | 5-6:3.5V | 3-4:4.5V | 1-2:5V | FAN | REMOTE RESET | PCIe1 | PCIe2 | 2 OF 12 | PRIMARY SILKSCREEN | T1023RDB-PC
L2_GND: 5 OF 12 | GROUND PLANE
L3_INT1: 6 OF 12 | INTERNAL SIGNAL 1
L4_INT2: 7 OF 12 | INTERNAL SIGNAL 2
L5_PWR: 8 OF 12  POWER PLANE
DIMENSION: Layer | L1 | L2 | L3 | L4 | L5 | L6 | width/spacing | GND | PWR | Type | SE Zo 40ohm | 7.0 mil | N/A | SE Zo 50ohm | 6.0 mil | 5.0 mil | DIFF Zo 100ohm | 4.1/7.8 mil | 4.1/10.5mil | DIFF Zo 90ohm | 4.3/4.5 mil | 4.3/5.8 mil | 5.1/4.5 mil | 4.8/5.1 mil | DIFF Zo 80ohm | 0.062 THK +/-10% | ALL THROUGH HOLE VIAS ARE PLUGGED WITH SOLDERMASK. | 21. FINISHED PCB MUST BE PANELIZED FOR ASSEMBLY ACCORDING TO CONTRACT MANUFACTURING REQUIREMENT. | ADD 2 SIDE RAILS .150" ON VERTICAL SIDE OF EACH BOARD WHERE SHOWN SEPARATED BY SCORING. | 16 | 22 | 17 | 21 | 8 | PRIMARY DATUM | GRID ORIGIN | VIEWED FROM PRIMARY SIDE | 2 X SIDE RAILS | DETAIL B | IMPEDANCE TABLE
DISPLAY_TOP: 1.5V PWR | CLOCK
User.8: CPLD | FLASH | SD CARD | BATTERY | BDM | P1020 | 1.2V PWR | 2.5V PWR | CPU VDD PWR | 3.3V PWR | MINI-PCIE | JTAG | 5.0V PWR | POE MODULE
User.14: 05-11-15 | 05-15-15 | 12-30-14 | R.Y. | C | C1 | B | ORIGINAL RELEASE | DDR DATA SWAP | CHANGE PCTe CARD | RESPIN PER SCHEMATIC
User.16: FIGURE | SIZE | 8.0 | 10.0 | 20.0 | 28.0 | 35.0 | 39.0 | 40.0 | 42.0 | 43.0 | 45.0 | 51.0 | 62.0 | 63.0 | 125.0 | 126.0 | 44.0 | 60.0 | 96.0 | 124.0 | 128.0 | 146.0 | 98.0x47.0 | 118.0x31.0 | 137.799x31.5 | DRILL CHART: TOP to BOTTOM | ALL UNITS ARE IN MILS | TOLERANCE | +0.0/-8.0 | +0.0/-10.0 | +2.0/-2.0 | +3.0/-3.0 | +4.0/-0.0 | PLATED | NON-PLATED | QTY | 711 | 2042 | 516 | 34 | 71 | 2 | 40 | 8 | 12 | 4 | 6 | 1
